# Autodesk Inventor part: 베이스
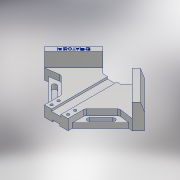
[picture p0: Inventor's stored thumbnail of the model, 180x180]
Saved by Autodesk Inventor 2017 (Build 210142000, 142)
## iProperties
Part Number: 베이스
Material: 알루미늄 6061
Document SubType Name: Modeling
Designer: 00-00
Mass: 571.315 g
Surface Area: 406.979 cm^2
Volume: 211.598 cm^3
Density: 2.7 g/cm^3
Appearance: 알루미늄 - 평지
Author: 00-00
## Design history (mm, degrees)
sketch "스케치1"
  geometry: L1 (-84.853, 0)-(0, -84.853); L2 (0, -84.853)-(84.853, 0); L3 (84.853, 0)-(0, 84.853); L4 (0, 84.853)-(-84.853, 0); 1 further point
  constraints: 8 end point, 2 horizontal alignment, 2 parallel, 2 vertical alignment, 1 perpendicular
  dimensions: "d0" = 120 distance of L3.end L1.start
extrude "돌출1" new body sketch "스케치1" distance "d1" = 18; taper "d2" = 0 deg
sketch "스케치2"
  geometry: L1 (-84.853, 0)-(0, -84.853) reference; L2 (84.853, 0)-(0, 84.853) reference; L3 (0, 84.853)-(-84.853, 0) reference; L4 (0, -84.853)-(-20, -84.853); L5 (-20, -84.853)-(-20, -64.853); L6 (-20, -64.853)-(0, -64.853); L7 (0, -64.853)-(0, -84.853); L8 (0, -64.853)-(0, 30.147); L9 (-16.005, 30.147)-(16.005, 30.147); L10 (16.005, 30.147)-(35.355, 49.497); L11 (-16.005, 30.147)-(-35.355, 49.497); 1 further point
  constraints: 16 end point, 3 perpendicular, 3 point on line, 2 horizontal, 2 parallel, 1 midpoint, 1 vertical
  dimensions: "d3" = 20 distance of L4.end L5.end; "d4" = 95 distance of L6.end L8.end; "d5" = 50 distance from line of L11 L2.end; "d6" = 50 distance from line of L10 L2.end
extrude "돌출2" cut sketch "스케치2" distance "d7" = 100; taper "d8" = 0 deg
extrude "돌출3" cut sketch "스케치2" distance "d9" = 100; taper "d10" = 0 deg
sketch "스케치3"
  geometry: L1 (-35.355, 49.497)-(-84.853, 0) reference; L2 (-84.853, 0)-(-20, -64.853) reference; L3 (-35.355, 49.497)-(-16.005, 30.147) reference; L4 (-24.749, 38.891)-(-74.246, -10.607); L5 (-74.246, -10.607)-(-49.497, -7.071); L6 (-49.497, -7.071)-(-20, -36.569); L7 (-29.698, -38.184)-(-49.497, -18.385); L8 (-32.527, -41.012)-(-52.326, -21.213); L9 (-46.669, -15.556)-(-26.87, -35.355); L10 (-20, -64.853)-(-20, -36.569); L11 (-68.059, -9.723)-(-20, -57.782); A1 r 4 centre (-29.698, -38.184) between (-32.527, -41.012) and (-26.87, -35.355); A2 r 4 centre (-49.497, -18.385) between (-46.669, -15.556) and (-52.326, -21.213); 2 further points
  constraints: 18 end point, 4 point on circle, 4 point on line, 4 tangent, 3 parallel, 2 centre point, 1 midpoint, 1 perpendicular, 1 vertical
  dimensions: "d11" = 15 distance between parallel lines of L1 L4; "d12" = 30 distance from line of L1 L5.end; "d13" = 20 distance between parallel lines of L6 L2; "d15" = 5 distance between parallel lines of L11 L2; "d16" = 12 distance from line of point (-39.598, -28.284) L2; "d17" = 8 distance between parallel lines of L9 L8; "d18" = 38 distance from line of L7.end L1; "d19" = 28 distance of L7.start L7.end
extrude "돌출4" join sketch "스케치3" distance "d20" = 24; taper "d21" = 0 deg
extrude "돌출5" cut sketch "스케치3" distance "d22" = 24; taper "d23" = 0 deg
extrude "돌출6" cut sketch "스케치3" distance "d24" = 10; taper "d25" = 0 deg
extrude "돌출7" cut sketch "스케치3" distance "d26" = 100; taper "d27" = 0 deg
sketch "스케치4"
  geometry: L1 (-20, -64.853)-(20, -64.853) reference; L2 (-14, -46.853)-(14, -46.853); L3 (14, -46.853)-(14, -58.853); L4 (14, -58.853)-(-14, -58.853); L5 (-14, -58.853)-(-14, -46.853); 7 further points
  constraints: 8 end point, 4 coincident, 2 midpoint, 2 parallel, 1 horizontal, 1 perpendicular, 1 vertical alignment
  dimensions: "d28" = 6 distance between parallel lines of L4 L1; "d29" = 12 distance between parallel lines of L2 L4; "d54" = 28 distance of L3.end L4.end
sketch "스케치5"
  geometry: L1 (40, 0)-(0, 0) reference; L2 (0, 18)-(40, 18) reference; L3 (12, 18)-(28, 18); L4 (28, 18)-(28, 14.5); L5 (28, 14.5)-(12, 14.5); L6 (12, 14.5)-(12, 18); L7 (14, 0)-(26, 0); L8 (26, 0)-(26, 3); L9 (26, 3)-(14, 3); L10 (14, 3)-(14, 0); 5 further points
  constraints: 16 end point, 4 midpoint, 4 parallel, 2 coincident, 2 horizontal, 2 perpendicular, 2 point on line
  dimensions: "d44" = 3.5 distance of L3.end L4.end; "d45" = 3 distance of L7.end L8.end; "d46" = 12 distance of L8.end L9.end; "d47" = 16 distance of L4.end L5.end
extrude "돌출8" cut sketch "스케치5" distance "d48" = 200; taper "d49" = 0 deg
sketch "스케치6"
  geometry: L1 (15, 0)-(0, 0) reference; L2 (5, 0)-(0, 15); L3 (0, 42)-(0, 0) reference; L4 (5, 0)-(0, 0); L5 (0, 15)-(0, 0); 1 further point
  constraints: 6 end point, 2 point on line, 1 collinear, 1 perpendicular
  dimensions: "d50" = 5 distance of L2.start L1.end; "d51" = 15 distance of L1.end L2.end
extrude "돌출9" cut sketch "스케치6" distance "d52" = 200; taper "d53" = 0 deg
hole "구멍3" sketch "스케치4" diameter "d55" = 8; stored, may be unused: countersink angle "d59" = 90 deg, drill point angle "d61" = 118 deg; dims "d56" = 6, "d57" = 4, "d58" = 2, "d60" = 10
hole "구멍4" sketch "스케치4" diameter "d62" = 4.5; stored, may be unused: countersink angle "d66" = 90 deg, drill point angle "d68" = 118 deg; dims "d63" = 6, "d64" = 4, "d65" = 2, "d67" = 10
sketch "스케치7"
  geometry: L1 (-74.246, -10.607)-(-24.749, 38.891) reference; L2 (-24.749, 38.891)-(-31.82, 45.962) reference; 2 further points
  constraints: 1 other
  dimensions: "d69" = 5 distance from line of L1 point (-53.033, 17.678); "d70" = 35 distance from line of L2 point (-53.033, 17.678)
feature "엠보싱1" sketch "스케치7" dims "d0" = 120, "d71" = 0.5, "d72" = 0
fillet "모깎기1" dims "d73" = 5
node "솔리드1"
mirror "미러1"
mirror "미러2"
mirror "미러3"
